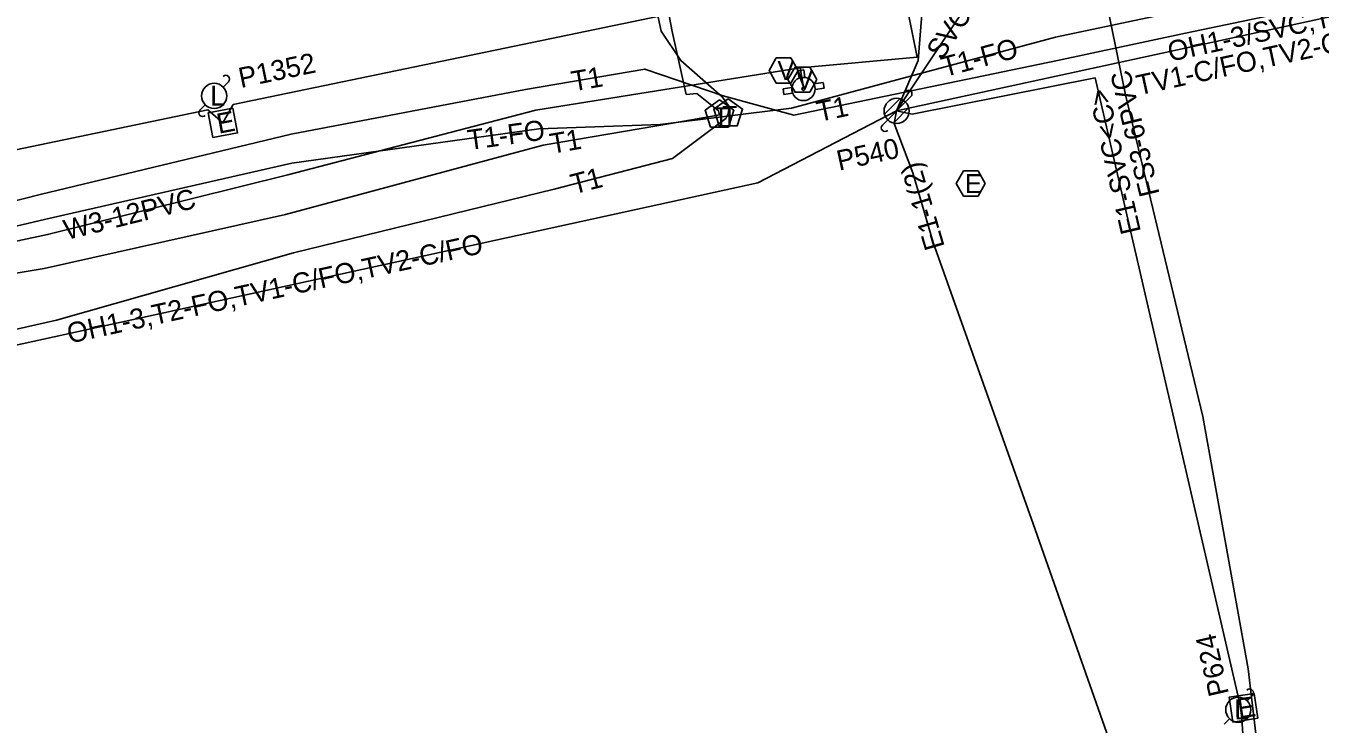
# Model space of a CAD drawing. Extents: x 2336688 to 2352634, y 362473 to 369571.
# Drawn here: x 2347760 to 2348017.1, y 367300.5 to 367439.2 of the extents above; entities that cross this region are included whole.
import ezdxf

# ---------------------------------------------------------------- set-up
doc = ezdxf.new("R2010")
doc.units = 0
for name, color, linetype in [('RD_EX_DV_Prop', 7, 'Continuous'), ('RD_EX_DV_TX_Prop', 7, 'Continuous'), ('RD_EX_RW', 7, 'Continuous'), ('RD_EX_RW_TX', 7, 'Continuous'), ('RD_HC_Data_Tic', 7, 'Continuous'), ('RD_PD_CstnLmt', 7, 'Continuous'), ('RD_PD_Final_TrvlWay', 7, 'Continuous'), ('RD_PD_PatLn4', 7, 'Continuous'), ('RD_SHT_ShtClip', 7, 'Continuous'), ('RD_Sketch1', 7, 'Continuous'), ('RD_Sketch2', 7, 'Continuous'), ('RD_Sketch5', 7, 'Continuous')]:
    doc.layers.add(name, color=color, linetype=linetype)

msp = doc.modelspace()

# ---------------------------------------------------------------- linework, layer by layer
at = {"layer": 'RD_EX_RW_TX'}
for points in [[(2347714.77, 367382.86), (2347763.63, 367391.02), (2347811.53, 367401.75), (2347862.77, 367415.49), (2347888.44, 367419.91), (2347896.74, 367421.34), (2347897.79, 367421.54), (2347897.61, 367422.37), (2347893.27, 367425.8), (2347891.17, 367425.6), (2347888.41, 367438.13), (2347885.63, 367452.77), (2347874.57, 367490.15), (2347868.31, 367529.39), (2347865.55, 367545.13), (2347870.25, 367553.68), (2347885.67, 367555.24), (2347935.15, 367566.81), (2347983.37, 367579.12), (2348035.16, 367587.36)], [(2347720.23, 367370.45), (2347766.06, 367380.72), (2347813.13, 367394.11), (2347864.91, 367406.78), (2347888.47, 367412.88), (2347899.03, 367420.8), (2347899.5, 367421.76), (2347899.71, 367423.2), (2347898.32, 367425.13), (2347890.1, 367432.34), (2347886.2, 367438.15), (2347883.23, 367452.15), (2347873.38, 367489.92), (2347867.11, 367529.21), (2347864.56, 367544.75), (2347867.1, 367555.1), (2347884.85, 367557.4), (2347935.07, 367567.56), (2347983.07, 367579.65), (2348008.15, 367584.51), (2348034.95, 367588.04)], [(2347470.17, 367338.02), (2347527.74, 367350.46), (2347547.36, 367354.41), (2347551.42, 367355.46), (2347554.94, 367356.11), (2347601.32, 367363.67), (2347672.79, 367378.26), (2347716.22, 367388.49), (2347732.21, 367393.25), (2347737, 367394.55), (2347740.32, 367395.23), (2347763.96, 367400.82), (2347812.85, 367411.94), (2347861.88, 367418.78), (2347886.02, 367419.64), (2347912.08, 367422.89), (2347964.53, 367437), (2348014.8, 367447.66), (2348042.92, 367455.01), (2348073.57, 367461.89), (2348119.92, 367473.29), (2348155.43, 367480.43), (2348206.38, 367490.17), (2348251.79, 367501.21)], [(2348044, 367448.64), (2348015.43, 367443.03), (2347990.39, 367437.77), (2347964.96, 367432.37), (2347912.55, 367421.46), (2347898.51, 367425.33), (2347882.92, 367430.65), (2347859.25, 367426.6), (2347812.67, 367417.74), (2347762.8, 367405.7), (2347714.95, 367393.51)]]:
    msp.add_lwpolyline(points, dxfattribs=at)
for points in [[(2347897.79, 367424.54), (2347894.93, 367422.47), (2347896.02, 367419.11), (2347899.55, 367419.11), (2347900.64, 367422.47)], [(2347899.5, 367424.76), (2347896.65, 367422.69), (2347897.74, 367419.34), (2347901.27, 367419.34), (2347902.36, 367422.69)]]:
    msp.add_lwpolyline(points, close=True, dxfattribs=at)
at = {"layer": 'RD_HC_Data_Tic'}
for p, q in [((2347799.17, 367427.07), (2347800.23, 367428.13)), ((2347935.8, 367425.16), (2347934.74, 367424.1)), ((2347794.57, 367422.48), (2347795.63, 367423.54)), ((2347933.62, 367424.75), (2347930.56, 367421.68)), ((2347934.74, 367424.1), (2347931.2, 367420.56)), ((2347935.39, 367422.98), (2347932.32, 367419.92)), ((2347931.2, 367420.56), (2347930.14, 367419.5)), ((2348002.6, 367305.13), (2348003.65, 367306.2)), ((2347998.05, 367300.49), (2347999.1, 367301.56))]:
    msp.add_line(p, q, dxfattribs=at)
for centre in [(2347797.4, 367425.31), (2347932.97, 367422.33), (2348000.85, 367303.35)]:
    msp.add_circle(centre, 2.5, dxfattribs=at)
for centre, start, end in [((2347799.7, 367428.66), 315, 135), ((2347935.27, 367425.69), 315, 135), ((2347795.1, 367421.95), 135, 315), ((2347930.67, 367418.97), 135, 315), ((2348003.11, 367306.73), 315.5955, 135.5955)]:
    msp.add_arc(centre, 0.75, start, end, dxfattribs=at)
at = {"layer": 'RD_PD_Final_TrvlWay'}
for points in [[(2347673.31, 367399.66), (2347678.14, 367397.96), (2347796.1, 367422.52), (2347799.13, 367419.97), (2347801.17, 367423.58), (2347934.37, 367451.31), (2347934.6, 367451.36), (2347939.01, 367454.97), (2347937.23, 367432.36), (2347932.97, 367422.33)], [(2347932.97, 367422.33), (2347936.06, 367421.7), (2347972.44, 367428.9), (2348001.42, 367303.39), (2348008.91, 367194.49), (2348010.46, 367172.01), (2348038.36, 367093.75), (2348042.62, 367092.02), (2348040.79, 367086.93), (2348072.37, 366998.38), (2348080, 366995.12), (2348075.41, 366989.83), (2348088.54, 366953.03)], [(2347932.97, 367422.33), (2347932.51, 367419.85), (2347936.17, 367410.01), (2347940.24, 367396.21), (2347960.13, 367340.28), (2347975.51, 367296.47), (2347988.87, 367253.06), (2347996.98, 367211.5), (2348008.18, 367165.5)]]:
    msp.add_lwpolyline(points, dxfattribs=at)
for points in [[(2347801.12, 367422.89), (2347796.21, 367421.97), (2347797.13, 367417.05), (2347802.04, 367417.97)], [(2347950.59, 367407.89), (2347949.15, 367410.39), (2347946.26, 367410.39), (2347944.82, 367407.89), (2347946.26, 367405.39), (2347949.15, 367405.39)], [(2348003.98, 367306.58), (2347999.03, 367305.83), (2347999.79, 367300.89), (2348004.73, 367301.64)]]:
    msp.add_lwpolyline(points, close=True, dxfattribs=at)
at = {"layer": 'RD_SHT_ShtClip'}
for q in [(2347960.39, 367463.55), (2348085.42, 367455.46)]:
    msp.add_line((2347932.97, 367422.33), q, dxfattribs=at)
msp.add_lwpolyline([(2347684.57, 367367.93), (2347715.59, 367366.51), (2347905.38, 367408.07), (2347932.97, 367422.33)], dxfattribs=at)
at = {"layer": 'RD_Sketch2'}
for p, q in [((2347914.51, 367430.47), (2347913.37, 367430.29)), ((2347913.37, 367430.29), (2347913.6, 367428.83)), ((2347914.74, 367428.99), (2347914.51, 367430.47)), ((2347918.39, 367427.97), (2347916.55, 367427.69)), ((2347918.56, 367426.83), (2347918.39, 367427.97)), ((2347912.17, 367427.01), (2347910.4, 367426.73)), ((2347910.4, 367426.73), (2347910.57, 367425.59)), ((2347910.57, 367425.59), (2347912.31, 367425.86)), ((2347916.77, 367426.55), (2347918.56, 367426.83))]:
    msp.add_line(p, q, dxfattribs=at)
for points in [[(2347470.35, 367337.23), (2347531.2, 367351.47), (2347577.01, 367360.75), (2347616.5, 367369.7), (2347668.2, 367379.09), (2347714.88, 367387.21), (2347764.3, 367397.77), (2347812.02, 367409.64), (2347861.32, 367422.45), (2347913.79, 367430.89), (2347937.03, 367433), (2347933.07, 367452.68), (2347964.62, 367460.29), (2348009.08, 367466.62), (2348042.26, 367474.52), (2348049.97, 367475.89), (2348057.53, 367476.89), (2348069.08, 367477.92), (2348103, 367487.1), (2348151.7, 367499.89), (2348204.32, 367511.65), (2348252.13, 367524.59)], [(2347913.79, 367430.89), (2347914.43, 367427.43), (2347914.46, 367426.69)]]:
    msp.add_lwpolyline(points, dxfattribs=at)
for points in [[(2347913.39, 367430.37), (2347911.95, 367432.87), (2347909.06, 367432.87), (2347907.62, 367430.37), (2347909.06, 367427.87), (2347911.95, 367427.87)], [(2347917.14, 367428.55), (2347915.7, 367431.05), (2347912.81, 367431.05), (2347911.37, 367428.55), (2347912.81, 367426.05), (2347915.7, 367426.05)]]:
    msp.add_lwpolyline(points, close=True, dxfattribs=at)
for radius in [2.31, 0.289]:
    msp.add_circle((2347914.46, 367426.69), radius, dxfattribs=at)
for start, end in [(83.0411, 112.0084), (356.4806, 25.4569), (172.1343, 201.1106)]:
    msp.add_arc((2347914.46, 367426.69), 2.31, start, end, dxfattribs=at)
at = {"layer": 'RD_Sketch5'}
msp.add_lwpolyline([(2347952.57, 367563.69), (2347952.6, 367563.53), (2347954.79, 367551.06), (2347962.49, 367508.35), (2347969.55, 367468.84), (2347978.45, 367425.53), (2347993.78, 367361.64), (2348002.84, 367311.48), (2348007.49, 367271.6), (2348009.48, 367222.84), (2348015.7, 367168.77), (2348038.63, 367106.93)], dxfattribs=at)

# ---------------------------------------------------------------- texts
at = {"layer": 'RD_EX_DV_Prop'}
for s, rotation, p in [('E1-SVC<C>', 103.001, (2347981.54, 367398.36)), ('E1-1(2)', 106.4381, (2347942.57, 367395.38))]:
    msp.add_text(s, height=4, rotation=rotation, dxfattribs=at).set_placement(p)
at = {"layer": 'RD_EX_DV_TX_Prop'}
for s, rotation, p in [('P1352', 11.7539, (2347802.69, 367426.87)), ('P540', 12.353, (2347921.55, 367410.43)), ('P624', 103.001, (2347999.01, 367306.55))]:
    msp.add_text(s, height=4, rotation=rotation, dxfattribs=at).set_placement(p)
at = {"layer": 'RD_EX_RW'}
for s, rotation, p in [('T1-FO', 15.0548, (2347942.5, 367429.02)), ('T1', 9.7095, (2347868.71, 367426.19)), ('T1', 11.7578, (2347917.56, 367420.14)), ('T1-FO', 7.9365, (2347848.01, 367414.53)), ('T1', 9.7834, (2347864.44, 367413.79)), ('T1', 14.521, (2347868.82, 367405.73))]:
    msp.add_text(s, height=4, rotation=rotation, dxfattribs=at).set_placement(p)
at = {"layer": 'RD_EX_RW_TX'}
for p in [(2347896.56, 367419.31), (2347898.27, 367419.54)]:
    msp.add_text('T', height=3.75, dxfattribs=at).set_placement(p)
at = {"layer": 'RD_HC_Data_Tic'}
for rotation, p in [(360, (2347796.59, 367423.37)), (0.5955, (2348000.06, 367301.4))]:
    msp.add_text('L', height=4, rotation=rotation, dxfattribs=at).set_placement(p)
at = {"layer": 'RD_PD_CstnLmt'}
msp.add_text('W3-12PVC', height=4, rotation=13.9616, dxfattribs=at).set_placement((2347768.09, 367396.66))
at = {"layer": 'RD_PD_Final_TrvlWay'}
for rotation, p in [(10.6261, (2347798.3, 367417.78)), (8.6895, (2348000.99, 367301.57))]:
    msp.add_text('E', height=4, rotation=rotation, dxfattribs=at).set_placement(p)
msp.add_text('E', height=3.75, dxfattribs=at).set_placement((2347946.57, 367406.02))
at = {"layer": 'RD_PD_PatLn4'}
for s, rotation, p in [('SVC/TF2', 56.3634, (2347941.97, 367432.27)), ('OH1-3/SVC,T2-FO,', 12.2611, (2347987.3, 367432.09)), ('TV1-C/FO,TV2-C/FO,TF2', 12.2611, (2347981.09, 367425.41)), ('OH1-3,T2-FO,TV1-C/FO,TV2-C/FO', 12.353, (2347768.64, 367376.08))]:
    msp.add_text(s, height=4, rotation=rotation, dxfattribs=at).set_placement(p)
at = {"layer": 'RD_Sketch1'}
msp.add_text('FS3-6PVC', height=4, rotation=103.492, dxfattribs=at).set_placement((2347985.23, 367405.84))
at = {"layer": 'RD_Sketch2'}
for p in [(2347909.29, 367428.5), (2347913.04, 367426.67)]:
    msp.add_text('V', height=3.75, dxfattribs=at).set_placement(p)

doc.saveas('drawing.dxf')
